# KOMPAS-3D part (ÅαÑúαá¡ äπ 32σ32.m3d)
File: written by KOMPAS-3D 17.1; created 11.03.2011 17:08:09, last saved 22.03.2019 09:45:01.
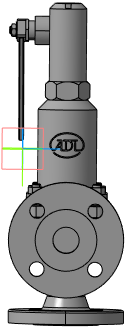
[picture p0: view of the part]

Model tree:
1. Плоскость XY
2. Плоскость ZX
3. Плоскость ZY
4. Ось X
5. Ось Y
6. Ось Z
7. Начало координат
8. Операция без истории:2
